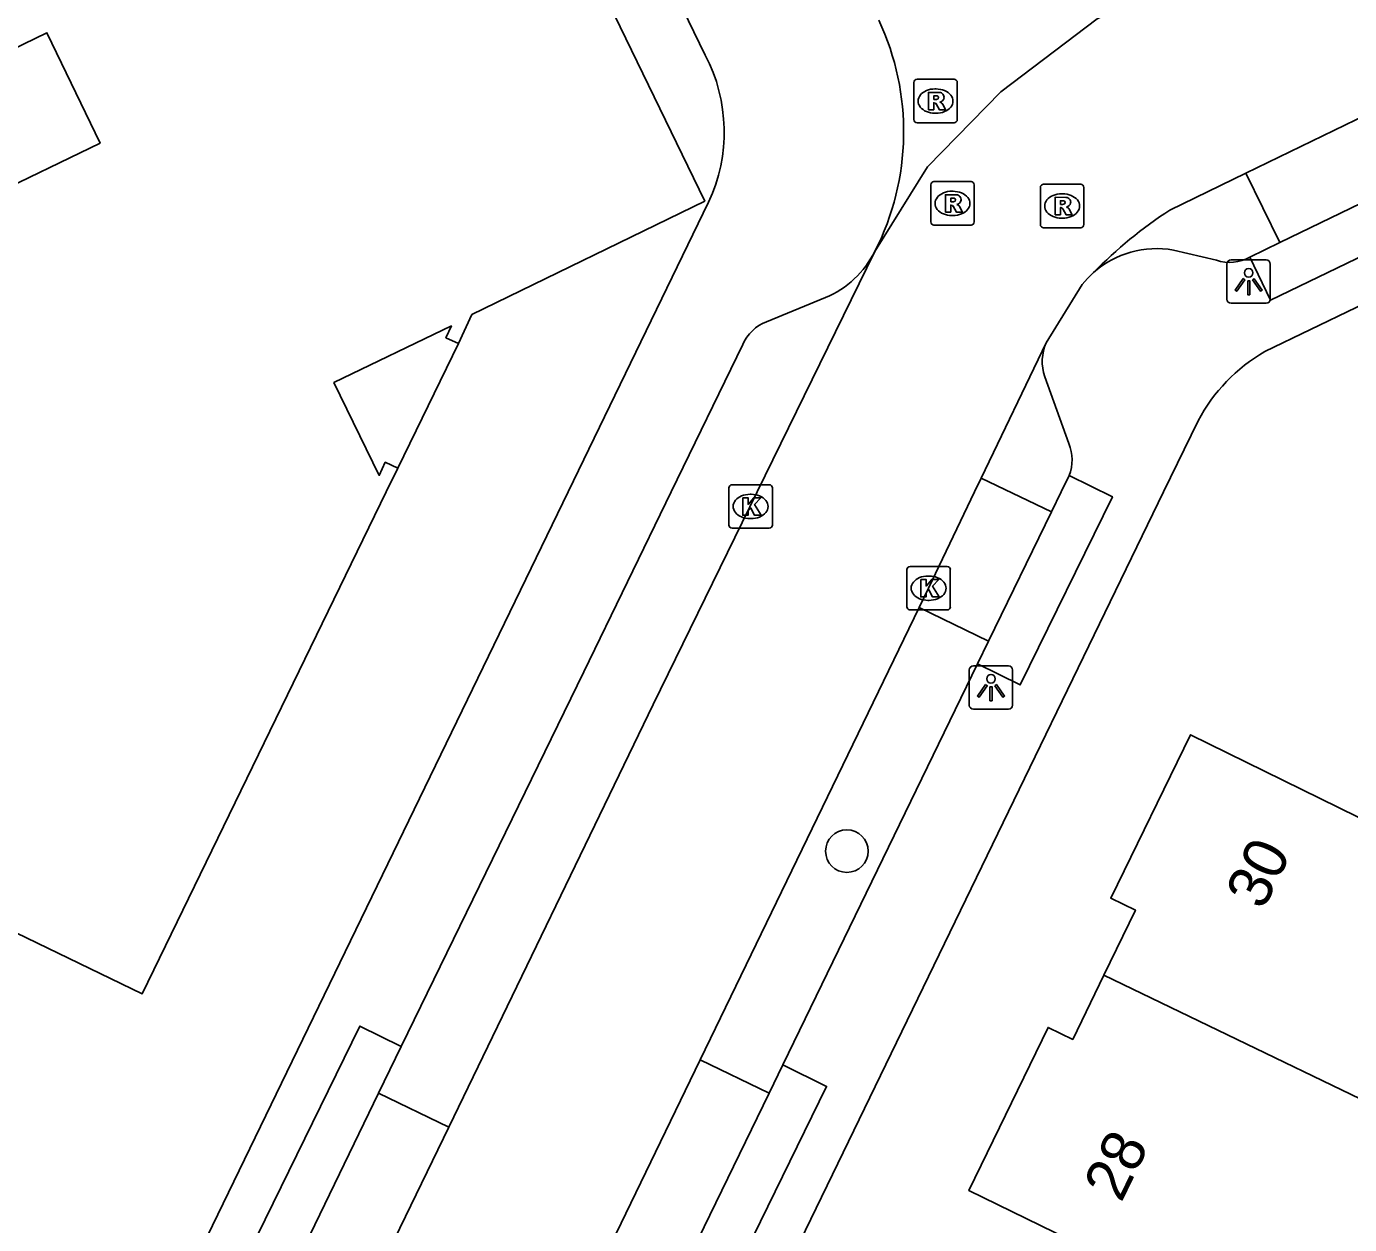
# Model space of a CAD drawing. Extents: x 160457 to 162082, y 388340 to 389736.
# Drawn here: x 160702.27 to 160732.69, y 388983.16 to 389010.7 of the extents above; entities that cross this region are included whole.
import ezdxf

# ---------------------------------------------------------------- set-up
doc = ezdxf.new("R2010")
doc.units = 0
for name, color, linetype in [('IMGEO_Boom', 7, 'Continuous'), ('IMGEO_Erf', 7, 'Continuous'), ('IMGEO_Kolk', 7, 'Continuous'), ('IMGEO_Lichtpunt', 7, 'Continuous'), ('IMGEO_Pand', 7, 'Continuous'), ('IMGEO_Pand_nummerreeks', 7, 'Continuous'), ('IMGEO_Pand_overbouw', 7, 'Continuous'), ('IMGEO_Parkeervlak_open', 7, 'Continuous'), ('IMGEO_Rijbaan_lokaal_gesloten', 7, 'Continuous'), ('IMGEO_Rioolput', 7, 'Continuous'), ('IMGEO_Voetpad_open', 7, 'Continuous')]:
    doc.layers.add(name, color=color, linetype=linetype)

msp = doc.modelspace()

# ---------------------------------------------------------------- linework, layer by layer
at = {"layer": 'IMGEO_Boom'}
msp.add_circle((160721.133, 388991.745), 0.489, dxfattribs=at)
at = {"layer": 'IMGEO_Erf'}
msp.add_lwpolyline([(160712.208, 389003.41), (160710.81, 389000.549)], dxfattribs=at)
at = {"layer": 'IMGEO_Kolk'}
for p, q in [((160718.419, 388999.241), (160718.419, 389000.093)), ((160718.494, 389000.167), (160719.346, 389000.167)), ((160719.42, 389000.093), (160719.42, 388999.241)), ((160718.907, 388999.947), (160718.932, 388999.947)), ((160718.93, 388999.387), (160718.905, 388999.387)), ((160719.346, 388999.167), (160718.494, 388999.167)), ((160722.511, 388997.363), (160722.511, 388998.215)), ((160722.586, 388998.289), (160723.438, 388998.289)), ((160723.512, 388998.215), (160723.512, 388997.363)), ((160722.999, 388998.069), (160723.024, 388998.069)), ((160723.438, 388997.289), (160722.586, 388997.289)), ((160723.022, 388997.509), (160722.997, 388997.509))]:
    msp.add_line(p, q, dxfattribs=at)
for points in [[(160718.419, 388999.241), (160718.419, 389000.093)], [(160718.494, 389000.167), (160719.346, 389000.167)], [(160719.42, 389000.093), (160719.42, 388999.241)], [(160718.74, 388999.867), (160718.863, 388999.867), (160718.863, 388999.716), (160718.993, 388999.867), (160719.157, 388999.867), (160719.011, 388999.716), (160719.164, 388999.467), (160719.012, 388999.467), (160718.927, 388999.631), (160718.863, 388999.564), (160718.863, 388999.467), (160718.74, 388999.467), (160718.74, 388999.867)], [(160719.346, 388999.167), (160718.494, 388999.167)], [(160722.511, 388997.363), (160722.511, 388998.215)], [(160722.586, 388998.289), (160723.438, 388998.289)], [(160723.512, 388998.215), (160723.512, 388997.363)], [(160722.832, 388997.989), (160722.955, 388997.989), (160722.955, 388997.838), (160723.085, 388997.989), (160723.249, 388997.989), (160723.103, 388997.838), (160723.256, 388997.589), (160723.104, 388997.589), (160723.019, 388997.753), (160722.955, 388997.686), (160722.955, 388997.589), (160722.832, 388997.589), (160722.832, 388997.989)], [(160723.438, 388997.289), (160722.586, 388997.289)]]:
    msp.add_lwpolyline(points, dxfattribs=at)
for centre, start, end in [((160718.496, 389000.091), 91.552, 178.448), ((160718.496, 389000.091), 91.552, 178.448), ((160719.344, 389000.091), 1.552, 88.448), ((160719.344, 389000.091), 1.552, 88.448), ((160718.496, 388999.243), 181.552, 268.448), ((160718.496, 388999.243), 181.552, 268.448), ((160719.344, 388999.243), 271.552, 358.448), ((160719.344, 388999.243), 271.552, 358.448), ((160722.588, 388998.213), 91.552, 178.448), ((160722.588, 388998.213), 91.552, 178.448), ((160723.436, 388998.213), 1.552, 88.448), ((160723.436, 388998.213), 1.552, 88.448), ((160722.588, 388997.365), 181.552, 268.448), ((160722.588, 388997.365), 181.552, 268.448), ((160723.436, 388997.365), 271.552, 358.448), ((160723.436, 388997.365), 271.552, 358.448)]:
    msp.add_arc(centre, 0.0765, start, end, dxfattribs=at)
for centre, major_axis, ratio, start_param, end_param in [((160718.906, 388999.667), (-0.387, 0.002), 0.722429, 4.712389, 7.853982), ((160718.931, 388999.667), (-0.39, 0.002), 0.717154, 1.570796, 4.712389), ((160722.998, 388997.789), (-0.387, 0.002), 0.722429, 4.712389, 7.853982), ((160723.023, 388997.789), (-0.39, 0.002), 0.717154, 1.570796, 4.712389)]:
    msp.add_ellipse(centre, major_axis=major_axis, ratio=ratio, start_param=start_param, end_param=end_param, dxfattribs=at)
at = {"layer": 'IMGEO_Lichtpunt'}
for p, q in [((160729.872, 389005.24), (160729.872, 389004.433)), ((160729.872, 389005.24), (160729.872, 389004.433)), ((160730.774, 389005.335), (160729.966, 389005.335)), ((160730.774, 389005.335), (160729.966, 389005.335)), ((160730.868, 389004.433), (160730.868, 389005.24)), ((160730.868, 389004.433), (160730.868, 389005.24)), ((160729.966, 389004.339), (160730.774, 389004.339)), ((160729.966, 389004.339), (160730.774, 389004.339)), ((160723.948, 388995.909), (160723.948, 388995.102)), ((160723.948, 388995.909), (160723.948, 388995.102)), ((160724.85, 388996.004), (160724.042, 388996.004)), ((160724.85, 388996.004), (160724.042, 388996.004)), ((160724.944, 388995.102), (160724.944, 388995.909)), ((160724.944, 388995.102), (160724.944, 388995.909)), ((160724.042, 388995.008), (160724.85, 388995.008)), ((160724.042, 388995.008), (160724.85, 388995.008))]:
    msp.add_line(p, q, dxfattribs=at)
for points in [[(160730.246, 389004.904), (160730.285, 389004.876), (160730.097, 389004.614), (160730.059, 389004.641), (160730.246, 389004.904)], [(160730.348, 389004.856), (160730.395, 389004.856), (160730.395, 389004.534), (160730.348, 389004.534), (160730.348, 389004.856)], [(160730.458, 389004.876), (160730.496, 389004.903), (160730.683, 389004.641), (160730.644, 389004.613), (160730.458, 389004.876)], [(160724.322, 388995.573), (160724.361, 388995.545), (160724.173, 388995.283), (160724.135, 388995.31), (160724.322, 388995.573)], [(160724.424, 388995.525), (160724.471, 388995.525), (160724.471, 388995.203), (160724.424, 388995.203), (160724.424, 388995.525)], [(160724.534, 388995.545), (160724.572, 388995.572), (160724.759, 388995.31), (160724.72, 388995.282), (160724.534, 388995.545)]]:
    msp.add_lwpolyline(points, dxfattribs=at)
for centre in [(160730.371, 389005.038), (160724.447, 388995.707)]:
    msp.add_circle(centre, 0.0994, dxfattribs=at)
for centre, start, end in [((160729.966, 389005.24), 90, 180), ((160729.966, 389005.24), 90, 180), ((160730.774, 389005.24), 0, 90), ((160730.774, 389005.24), 0, 90), ((160729.966, 389004.433), 180, 270), ((160729.966, 389004.433), 180, 270), ((160730.774, 389004.433), 270, 0), ((160730.774, 389004.433), 270, 360), ((160724.042, 388995.909), 90, 180), ((160724.042, 388995.909), 90, 180), ((160724.85, 388995.909), 0, 90), ((160724.85, 388995.909), 0, 90), ((160724.042, 388995.102), 180, 270), ((160724.042, 388995.102), 180, 270), ((160724.85, 388995.102), 270, 0), ((160724.85, 388995.102), 270, 360)]:
    msp.add_arc(centre, 0.0946, start, end, dxfattribs=at)
at = {"layer": 'IMGEO_Pand'}
for points in [[(160681.311, 389009.806), (160681.445, 389009.872), (160680.32, 389012.188), (160708.539, 389025.895), (160717.865, 389006.688), (160712.515, 389004.079), (160712.208, 389003.41)], [(160710.81, 389000.549), (160710.543, 389000), (160704.929, 388988.463), (160696.232, 388992.673), (160697.352, 388994.987), (160696.098, 388995.905), (160697.002, 388997.764), (160701.389, 389006.781), (160703.963, 389008.022), (160702.742, 389010.556), (160690.481, 389004.601), (160688.649, 389003.711), (160687.793, 389005.025), (160684.429, 389003.39)], [(160710.81, 389000.549), (160710.52, 389000.682), (160710.382, 389000.382), (160709.341, 389002.516), (160712.043, 389003.818), (160711.916, 389003.546), (160712.208, 389003.41)], [(160734.663, 388995.125), (160733.291, 388992.329), (160729.034, 388994.421), (160727.2, 388990.666), (160727.766, 388990.39), (160727.04, 388988.89)], [(160727.04, 388988.89), (160726.326, 388987.416), (160725.759, 388987.691), (160723.939, 388983.94), (160728.549, 388981.688), (160727.182, 388978.877)], [(160727.04, 388988.89), (160735.996, 388984.575), (160737.438, 388983.877)]]:
    msp.add_lwpolyline(points, dxfattribs=at)
at = {"layer": 'IMGEO_Pand_overbouw'}
msp.add_lwpolyline([(160684.429, 389003.39), (160685.392, 389001.409), (160686.098, 389000), (160689.872, 388992.464), (160690.248, 388992.282), (160694.941, 388990.006), (160696.232, 388992.673), (160704.929, 388988.463), (160710.543, 389000), (160710.81, 389000.549), (160710.52, 389000.682), (160710.382, 389000.382), (160709.341, 389002.516), (160712.043, 389003.818), (160711.916, 389003.546), (160712.208, 389003.41), (160712.515, 389004.079), (160717.865, 389006.688), (160708.539, 389025.895), (160680.32, 389012.188), (160681.445, 389009.872), (160681.311, 389009.806)], close=True, dxfattribs=at)
at = {"layer": 'IMGEO_Parkeervlak_open'}
for points in [[(160730.309, 389007.332), (160731.085, 389005.734)], [(160725.837, 388999.541), (160724.222, 389000.315)], [(160722.795, 388997.343), (160724.388, 388996.571)], [(160719.344, 388986.181), (160717.76, 388986.947)], [(160711.98, 388985.4), (160710.368, 388986.181)]]:
    msp.add_lwpolyline(points, dxfattribs=at)
at = {"layer": 'IMGEO_Rijbaan_lokaal_gesloten'}
for points in [[(160732.682, 389013.601), (160729.536, 389012.239), (160726.89, 389010.874), (160724.673, 389009.197), (160722.986, 389007.473), (160721.777, 389005.531)], [(160730.309, 389007.332), (160733.338, 389008.803)], [(160728.56, 389006.482), (160730.309, 389007.332)], [(160721.777, 389005.531), (160719.073, 389000), (160716.684, 388995.115), (160711.98, 388985.4)], [(160725.717, 389003.43), (160726.542, 389004.77), (160726.665, 389004.911), (160726.801, 389005.042)], [(160724.222, 389000.315), (160725.717, 389003.43)], [(160722.795, 388997.343), (160723.011, 388997.79), (160724.071, 389000), (160724.222, 389000.315)], [(160717.76, 388986.947), (160722.795, 388997.343)], [(160714.914, 388981.07), (160717.76, 388986.947)], [(160711.98, 388985.4), (160709.111, 388979.474), (160708.825, 388978.885)]]:
    msp.add_lwpolyline(points, dxfattribs=at)
for centre, radius, start, end in [((160716.407, 389008.28), 6.032, 332.8879, 25.1719), ((160734.556, 388997.363), 10.914, 123.3275, 135.2833)]:
    msp.add_arc(centre, radius, start, end, dxfattribs=at)
at = {"layer": 'IMGEO_Rioolput'}
for p, q in [((160722.671, 389008.56), (160722.671, 389009.412)), ((160722.746, 389009.486), (160723.598, 389009.486)), ((160723.672, 389009.412), (160723.672, 389008.56)), ((160723.159, 389009.266), (160723.184, 389009.266)), ((160723.182, 389008.706), (160723.157, 389008.706)), ((160723.598, 389008.486), (160722.746, 389008.486)), ((160723.061, 389006.208), (160723.061, 389007.06)), ((160723.136, 389007.134), (160723.988, 389007.134)), ((160724.062, 389007.06), (160724.062, 389006.208)), ((160725.582, 389006.148), (160725.582, 389007)), ((160725.657, 389007.074), (160726.509, 389007.074)), ((160726.583, 389007), (160726.583, 389006.148)), ((160723.549, 389006.914), (160723.574, 389006.914)), ((160726.07, 389006.854), (160726.095, 389006.854)), ((160723.988, 389006.134), (160723.136, 389006.134)), ((160723.572, 389006.354), (160723.547, 389006.354)), ((160726.509, 389006.074), (160725.657, 389006.074)), ((160726.093, 389006.294), (160726.068, 389006.294))]:
    msp.add_line(p, q, dxfattribs=at)
for points in [[(160722.671, 389008.56), (160722.671, 389009.412)], [(160722.746, 389009.486), (160723.598, 389009.486)], [(160723.672, 389009.412), (160723.672, 389008.56)], [(160723.26, 389009.184), (160723.008, 389009.186), (160723.008, 389008.786)], [(160723.186, 389009.105), (160723.132, 389009.105), (160723.132, 389009.024)], [(160723.008, 389008.786), (160723.132, 389008.786), (160723.132, 389008.948), (160723.143, 389008.948)], [(160723.132, 389009.024), (160723.184, 389009.024)], [(160723.19, 389008.919), (160723.261, 389008.786), (160723.401, 389008.786), (160723.336, 389008.912)], [(160723.598, 389008.486), (160722.746, 389008.486)], [(160723.061, 389006.208), (160723.061, 389007.06)], [(160723.136, 389007.134), (160723.988, 389007.134)], [(160724.062, 389007.06), (160724.062, 389006.208)], [(160725.582, 389006.148), (160725.582, 389007)], [(160725.657, 389007.074), (160726.509, 389007.074)], [(160726.583, 389007), (160726.583, 389006.148)], [(160723.65, 389006.832), (160723.398, 389006.834), (160723.398, 389006.434)], [(160723.576, 389006.753), (160723.522, 389006.753), (160723.522, 389006.672)], [(160723.522, 389006.672), (160723.574, 389006.672)], [(160726.171, 389006.772), (160725.919, 389006.774), (160725.919, 389006.374)], [(160726.097, 389006.693), (160726.043, 389006.693), (160726.043, 389006.612)], [(160723.398, 389006.434), (160723.522, 389006.434), (160723.522, 389006.596), (160723.533, 389006.596)], [(160723.58, 389006.567), (160723.651, 389006.434), (160723.791, 389006.434), (160723.726, 389006.56)], [(160725.919, 389006.374), (160726.043, 389006.374), (160726.043, 389006.536), (160726.054, 389006.536)], [(160726.043, 389006.612), (160726.095, 389006.612)], [(160726.101, 389006.507), (160726.172, 389006.374), (160726.312, 389006.374), (160726.247, 389006.5)], [(160723.988, 389006.134), (160723.136, 389006.134)], [(160726.509, 389006.074), (160725.657, 389006.074)]]:
    msp.add_lwpolyline(points, dxfattribs=at)
for centre, radius, start, end in [((160722.748, 389009.41), 0.0765, 91.552, 178.448), ((160722.748, 389009.41), 0.0765, 91.552, 178.448), ((160723.596, 389009.41), 0.0765, 1.552, 88.448), ((160723.596, 389009.41), 0.0765, 1.552, 88.448), ((160723.192, 389009.009), 0.0964, 77.0061, 93.1865), ((160723.206, 389009.066), 0.0378, 276.6634, 79.6772), ((160723.259, 389009.074), 0.109, 350.3612, 89.416), ((160723.142, 389008.895), 0.0533, 26.0293, 88.6989), ((160723.168, 389009.213), 0.19, 274.7715, 282.9687), ((160723.257, 389009.074), 0.112, 277.5842, 350.9817), ((160723.241, 389008.859), 0.108, 29.5134, 73.7905), ((160722.748, 389008.562), 0.0765, 181.552, 268.448), ((160722.748, 389008.562), 0.0765, 181.552, 268.448), ((160723.596, 389008.562), 0.0765, 271.552, 358.448), ((160723.596, 389008.562), 0.0765, 271.552, 358.448), ((160723.138, 389007.058), 0.0765, 91.552, 178.448), ((160723.138, 389007.058), 0.0765, 91.552, 178.448), ((160723.986, 389007.058), 0.0765, 1.552, 88.448), ((160723.986, 389007.058), 0.0765, 1.552, 88.448), ((160725.659, 389006.998), 0.0765, 91.552, 178.448), ((160725.659, 389006.998), 0.0765, 91.552, 178.448), ((160726.507, 389006.998), 0.0765, 1.552, 88.448), ((160726.507, 389006.998), 0.0765, 1.552, 88.448), ((160723.558, 389006.861), 0.19, 274.7715, 282.9687), ((160723.582, 389006.657), 0.0964, 77.0061, 93.1865), ((160723.596, 389006.714), 0.0378, 276.6634, 79.6772), ((160723.649, 389006.722), 0.109, 350.3612, 89.416), ((160723.647, 389006.722), 0.112, 277.5842, 350.9817), ((160726.103, 389006.597), 0.0964, 77.0061, 93.1865), ((160726.117, 389006.654), 0.0378, 276.6634, 79.6772), ((160726.17, 389006.662), 0.109, 350.3612, 89.416), ((160723.532, 389006.543), 0.0533, 26.0293, 88.6989), ((160723.631, 389006.507), 0.108, 29.5134, 73.7905), ((160726.053, 389006.483), 0.0533, 26.0293, 88.6989), ((160726.079, 389006.801), 0.19, 274.7715, 282.9687), ((160726.168, 389006.662), 0.112, 277.5842, 350.9817), ((160726.152, 389006.447), 0.108, 29.5134, 73.7905), ((160723.138, 389006.21), 0.0765, 181.552, 268.448), ((160723.138, 389006.21), 0.0765, 181.552, 268.448), ((160723.986, 389006.21), 0.0765, 271.552, 358.448), ((160723.986, 389006.21), 0.0765, 271.552, 358.448), ((160725.659, 389006.15), 0.0765, 181.552, 268.448), ((160725.659, 389006.15), 0.0765, 181.552, 268.448), ((160726.507, 389006.15), 0.0765, 271.552, 358.448), ((160726.507, 389006.15), 0.0765, 271.552, 358.448)]:
    msp.add_arc(centre, radius, start, end, dxfattribs=at)
for centre, major_axis, ratio, start_param, end_param in [((160723.158, 389008.986), (-0.387, 0.002), 0.722429, 4.712389, 7.853982), ((160723.183, 389008.986), (-0.39, 0.002), 0.717154, 1.570796, 4.712389), ((160723.548, 389006.634), (-0.387, 0.002), 0.722429, 4.712389, 7.853982), ((160723.573, 389006.634), (-0.39, 0.002), 0.717154, 1.570796, 4.712389), ((160726.069, 389006.574), (-0.387, 0.002), 0.722429, 4.712389, 7.853982), ((160726.094, 389006.574), (-0.39, 0.002), 0.717154, 1.570796, 4.712389)]:
    msp.add_ellipse(centre, major_axis=major_axis, ratio=ratio, start_param=start_param, end_param=end_param, dxfattribs=at)
at = {"layer": 'IMGEO_Voetpad_open'}
for points in [[(160709.241, 389027.834), (160717.878, 389010.043)], [(160734.998, 389007.624), (160735.477, 389006.634), (160730.876, 389004.411), (160730.397, 389005.401)], [(160730.743, 389003.227), (160740.195, 389007.778), (160741.546, 389005.109)], [(160731.085, 389005.734), (160734.118, 389007.199)], [(160717.954, 389006.662), (160714.723, 389000), (160704.109, 388978.111), (160691.138, 388951.382), (160678.026, 388924.35)], [(160729.63, 389005.329), (160728.642, 389005.561)], [(160730.397, 389005.401), (160731.085, 389005.734)], [(160719.285, 389003.915), (160720.643, 389004.468)], [(160710.888, 388987.255), (160715.085, 388995.868), (160717.091, 389000), (160718.738, 389003.391)], [(160725.682, 389002.647), (160726.235, 389001.116)], [(160702.377, 388946.323), (160728.414, 389000), (160729.207, 389001.634)], [(160726.244, 389000.376), (160727.238, 388999.89), (160725.121, 388995.564), (160724.133, 388996.048)], [(160725.837, 388999.541), (160726.061, 389000), (160726.244, 389000.376)], [(160724.388, 388996.571), (160725.837, 388999.541)], [(160724.133, 388996.048), (160724.388, 388996.571)], [(160724.133, 388996.048), (160719.66, 388986.831)], [(160706.937, 388979.099), (160705.949, 388979.583), (160709.933, 388987.723), (160710.888, 388987.255)], [(160710.888, 388987.255), (160710.368, 388986.181)], [(160719.66, 388986.831), (160720.668, 388986.338), (160716.954, 388978.748), (160715.966, 388979.232)], [(160719.344, 388986.181), (160719.66, 388986.831)], [(160710.368, 388986.181), (160707.213, 388979.668)], [(160716.489, 388980.308), (160719.344, 388986.181)]]:
    msp.add_lwpolyline(points, dxfattribs=at)
for centre, radius, start, end in [((160714.506, 389008.276), 3.807, 334.9206, 27.6548), ((160719.764, 389006.542), 2.253, 292.9691, 333.3289), ((160728.259, 389003.395), 2.2, 79.9771, 131.5105), ((160729.935, 389006.199), 0.922, 250.6636, 300.0619), ((160719.651, 389002.986), 0.998, 111.4782, 156.0612), ((160726.705, 389002.994), 1.08, 156.1721, 198.7091), ((160732.745, 388999.76), 4.003, 119.9995, 152.0878), ((160725.304, 389000.735), 1.006, 339.1206, 22.273)]:
    msp.add_arc(centre, radius, start, end, dxfattribs=at)

# ---------------------------------------------------------------- texts
at = {"layer": 'IMGEO_Pand_nummerreeks'}
for s, rotation, p in [('30', 63.9707, (160730.704, 388990.364)), ('28', 64.1172, (160727.44, 388983.644))]:
    msp.add_text(s, height=1, rotation=rotation, dxfattribs=at).set_placement(p)

doc.saveas('drawing.dxf')
